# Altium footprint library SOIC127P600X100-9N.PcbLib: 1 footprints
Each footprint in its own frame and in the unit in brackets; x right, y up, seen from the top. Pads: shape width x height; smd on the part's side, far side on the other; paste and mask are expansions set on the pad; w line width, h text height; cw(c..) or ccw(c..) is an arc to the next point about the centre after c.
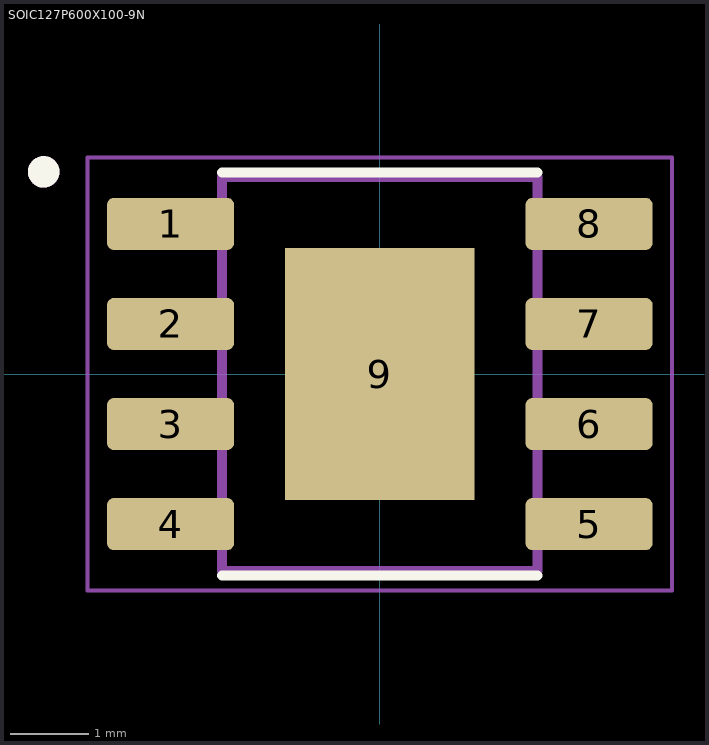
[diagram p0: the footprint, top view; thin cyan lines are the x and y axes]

## SOIC127P600X100-9N [mm]
pads (9):
  rrect25% 1.61x0.66 smd: 1(-2.655,1.905) 2(-2.655,0.635) 3(-2.655,-0.635) 4(-2.655,-1.905) 5(2.655,-1.905) 6(2.655,-0.635) 7(2.655,0.635) 8(2.655,1.905)
  rect 2.4x3.2 smd paste-3: 9(0,0)
Top Overlay:
  circle w0.2: c-4.265,2.565 r0.1
  lines w0.127: -2,-2.555 2,-2.555 ; -2,2.555 2,2.555
Top Paste:
  region: 0.935,0.135 0.135,0.135 0.135,1.335 0.935,1.335
  region: 0.935,-1.335 0.135,-1.335 0.135,-0.135 0.935,-0.135
  region: -0.135,-1.335 -0.935,-1.335 -0.935,-0.135 -0.135,-0.135
  region: -0.135,0.135 -0.935,0.135 -0.935,1.335 -0.135,1.335
Mechanical 13:
  circle w0.2: c-4.265,2.565 r0.1
  lines w0.127: -2,-2.5 -2,2.5 2,2.5 2,-2.5 -2,-2.5
Mechanical 15:
  lines w0.05: -3.71,-2.75 -3.71,2.75 3.71,2.75 3.71,-2.75 -3.71,-2.75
